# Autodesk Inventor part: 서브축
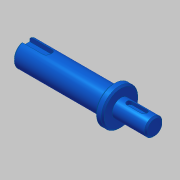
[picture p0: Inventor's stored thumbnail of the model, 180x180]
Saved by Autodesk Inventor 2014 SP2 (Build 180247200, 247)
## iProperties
Created: 2018-09
Part Number: 서브축
Document SubType Name: Modeling
Density: 1 g/cm^3
Material: 강철, 연강
Appearance: 청록색
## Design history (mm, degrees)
sketch "스케치1"
  geometry: L1 (-18.818, -7)-(-18.818, 7) reference; L2 (-41.331, -13.5)-(-41.331, 13.5) reference; L3 (-46.5, 12.249)-(-46.5, -12.249) reference; L4 (-18.331, 0)-(-106.5, 0); L5 (-18.331, 0)-(-18.331, -6); L6 (-18.331, -6)-(-41.331, -6); L7 (-41.331, -12.5)-(-46.5, -12.5); L8 (-46.5, -8.5)-(-106.5, -8.5); L9 (-106.5, -8.5)-(-106.5, 0); L10 (-46.5, -8.5)-(-46.5, -12.5); L11 (-41.331, -6)-(-41.331, -12.5); 2 further points
  constraints: 17 end point, 5 point on line, 3 parallel, 3 perpendicular, 2 collinear, 1 midpoint
  dimensions: "d0" = 23 distance between parallel lines of L2 L5; "d1" = 12 diameter of L6 L4; "d2" = 25 diameter of L7 L4; "d3" = 17 diameter of L8 L4; "d4" = 60 distance of L8.start L8.end
revolve "회전1" sketch "스케치1" stored, may be unused: angle "d5" = 90 deg
chamfer "모따기1" distance "d6" = 1; stored, may be unused: second distance "d7" = 2, angle "d8" = 45 deg
node "작업 평면1"
sketch "스케치2"
  geometry: L1 (11.5, 5)-(11.5, -5) reference; L2 (-5.5, -2)-(4.5, -2); L3 (4.5, 2)-(-5.5, 2); A1 r 2 centre (4.5, 0) between (4.5, -2) and (4.5, 2); A2 r 2 centre (-5.5, 0) between (-5.5, 2) and (-5.5, -2); 2 further points
  constraints: 4 end point, 4 point on circle, 4 tangent, 2 centre point, 1 horizontal alignment, 1 midpoint, 1 parallel, 1 perpendicular
  dimensions: "d9" = 4 distance between parallel lines of L2 L3; "d10" = 14 dimension on A1 A2; "d11" = 5 distance edge to line of A1 L1
extrude "돌출1" cut sketch "스케치2" distance "d12" = 2.5; taper "d13" = 0 deg
node "작업 평면2"
sketch "스케치3"
  geometry: L1 (-30, -7.5)-(-30, 7.5) reference; L2 (-30, 3)-(-15, 3); L3 (-15, -3)-(-30, -3); A1 r 3 centre (-15, 0) between (-15, -3) and (-15, 3); 2 further points
  constraints: 4 end point, 2 perpendicular, 2 point on circle, 2 point on line, 2 tangent, 1 centre point, 1 horizontal alignment, 1 midpoint
  dimensions: "d14" = 6 distance between parallel lines of L3 L2; "d15" = 18 dimension on A1 L1
extrude "돌출2" cut sketch "스케치3" distance "d16" = 3.5; taper "d17" = 0 deg
node "솔리드1"
node "참조1"
node "참조2"
node "참조3"
